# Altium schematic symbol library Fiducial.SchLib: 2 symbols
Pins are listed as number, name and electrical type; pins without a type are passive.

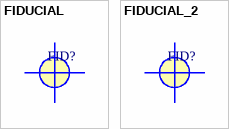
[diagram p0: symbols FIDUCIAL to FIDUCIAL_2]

## FIDUCIAL
designator FID?, comment Fiducial Marker  (value not drawn)
footprint FIDUCIAL (Fiducial marker)

## FIDUCIAL_2
designator FID?, comment Fiducial Marker  (value not drawn)
footprint FIDUCIAL2 (Fiducial marker)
